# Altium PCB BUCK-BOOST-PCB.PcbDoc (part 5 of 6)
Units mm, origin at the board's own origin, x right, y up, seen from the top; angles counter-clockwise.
Board outline 99.9 x 67.48 mm, 4 copper layers (Top Layer, POWER, GND, Bottom Layer); 181 components, 110 nets, 560 pads, 389 vias.
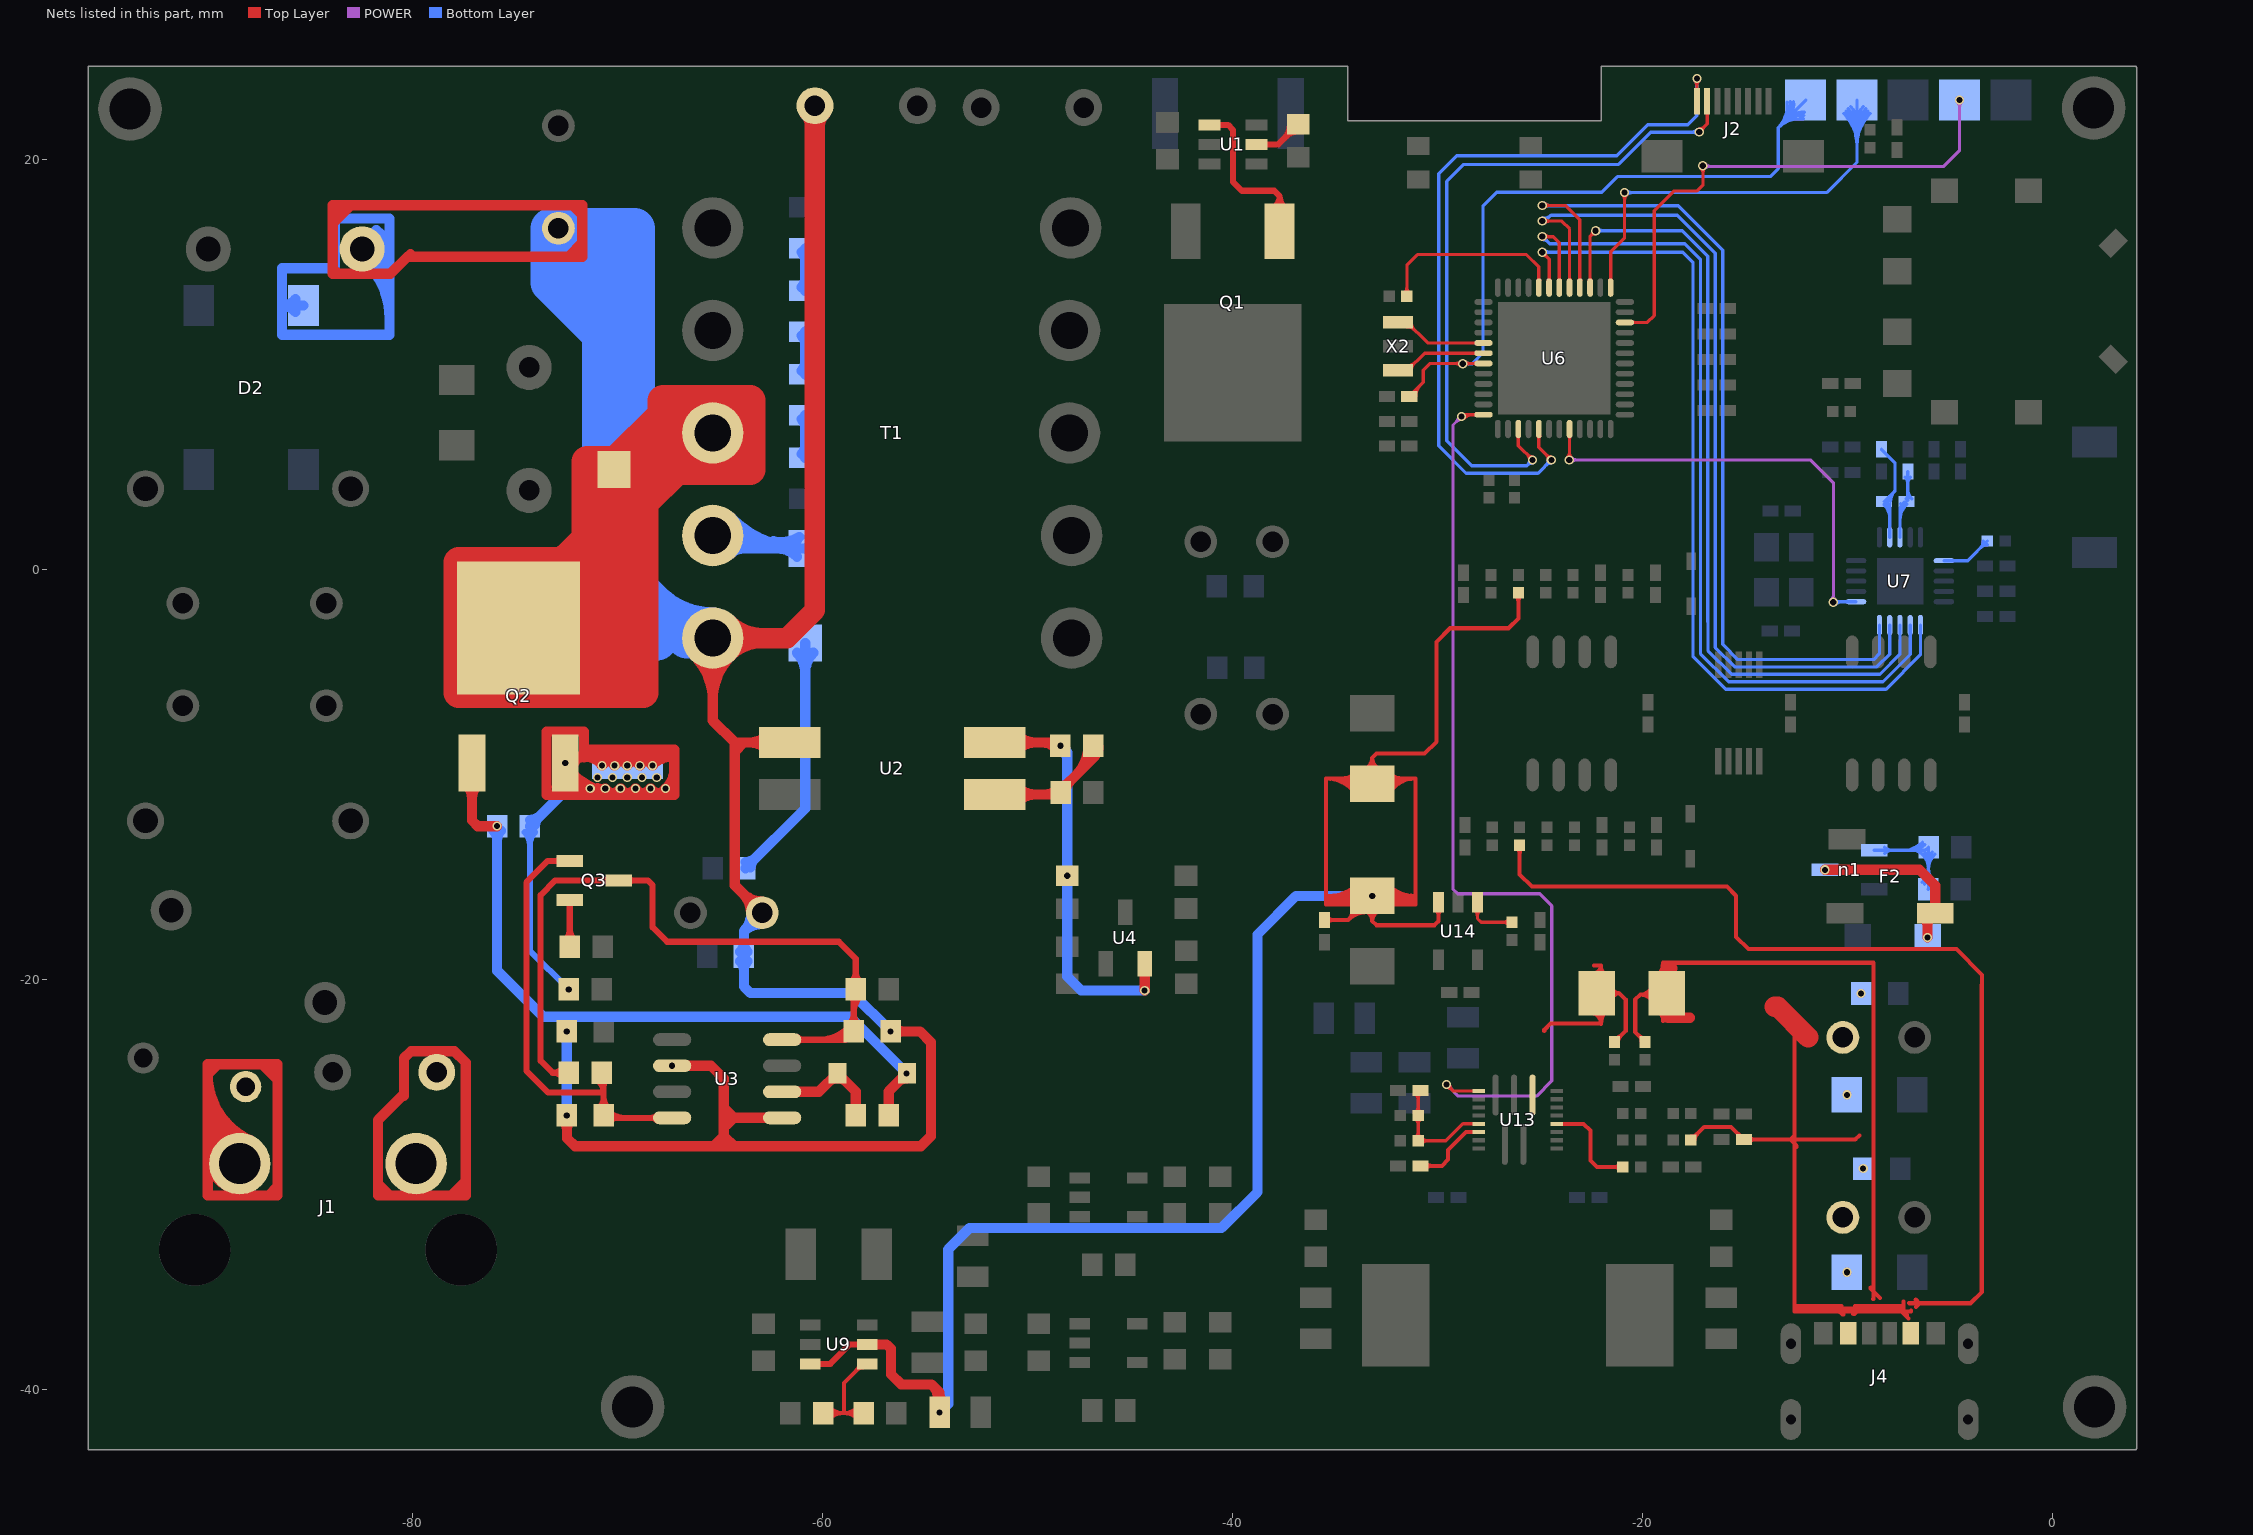
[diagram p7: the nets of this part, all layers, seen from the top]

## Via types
v1: diameter 0.45, hole 0.3, Top Layer to Bottom Layer, 389 vias

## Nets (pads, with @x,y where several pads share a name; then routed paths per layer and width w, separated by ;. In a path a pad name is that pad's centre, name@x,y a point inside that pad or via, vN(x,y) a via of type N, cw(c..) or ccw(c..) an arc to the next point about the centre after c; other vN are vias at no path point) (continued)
NetD1_1: D1.1 Q2.2 T1.3 | length 185.7
  Top Layer w1.5: Q2.2@-74.804,-2.841 Q2.2@-71.87,0.093 ; Q2.2@-72.595,-2.163 cw(c-68.589,-1.388) -71.474,1.497 ; Q2.2@-72.554,-2.591 cw(c-67.726,-2.591) -71.14,0.823 ; -72.258,0.714 cw(c-74.804,3.261) -74.804,-0.341 ccw(c-74.804,5.695) -70.536,1.427 ; Q2.2@-71.986,0.354 Q2.2@-72.617,0.354 ; -71.474,1.476 cw(c-66.828,1.476) -70.113,4.762 ccw(c-68.37,3.019) -70.836,3.019 ; -71.01,5.278 cw(c-71.01,4.131) D1.1@-70.199,4.942 ; D1.1@-70.199,4.762 cw(c-72.655,2.306) -69.181,2.306 ; D1.1@-70.177,4.748 cw(c-70.708,3.316) -69.181,3.316 ; D1.1@-70.176,4.748 cw(c-70.883,2.715) -68.731,2.715 ; D1.1@-70.16,4.744 cw(c-70.25,3.228) -68.731,3.228 ; D1.1@-70.113,4.942 cw(c-69.302,4.131) -69.302,5.278 ; D1.1@-69.999,5.323 -67.768,7.553 ; -67.768,6.422 -67.768,7.282 ; T1.3@-65.336,6.671 -66.486,5.522 ; Q2.2@-72.617,0.354 -77.719,0.354 -77.719,-5.989 Q2.2@-71.87,-5.989 ; Q2.2@-72.617,0.354 -71.474,1.497 ; Q2.2@-71.87,-5.989 Q2.2@-71.87,0.093 ; Q2.2@-71.87,-5.989 -71.218,-5.989 ; Q2.2@-71.87,0.093 -71.218,0.746 ; Q2.2@-71.87,0.093 -71.87,0.746 -71.218,0.746 ; -71.474,1.497 -70.836,2.136 ; -71.474,1.497 -71.474,5.278 D1.1@-70.836,5.278 ; -71.218,-5.989 -71.218,0.746 ; -71.218,-5.989 -70.156,-5.989 ; -71.218,0.745 cw(c-73.976,3.503) -74.501,-0.361 ccw(c-73.976,3.503) -71.218,0.745 ; -71.218,0.745 ccw(c-67.99,-2.483) -72.555,-2.555 cw(c-67.99,-2.483) -71.218,0.745 ; -71.218,0.746 -70.156,1.807 ; -70.836,2.136 D1.1@-70.836,5.278 ; -70.836,2.136 -70.725,2.136 -70.156,2.705 ; -70.836,2.136 -70.156,2.816 ; D1.1@-70.836,5.278 D1.1@-69.773,5.278 ; -70.156,-5.989 -69.181,-5.989 ; -70.156,-5.989 -70.156,1.807 ; -70.156,1.807 -70.156,2.705 ; -70.156,2.705 -69.181,3.68 ; -70.156,2.705 -70.156,2.816 ; -70.156,2.816 D1.1@-70.156,4.895 ; D1.1@-70.156,4.895 -68.731,4.895 ; D1.1@-70.156,4.895 D1.1@-69.773,5.278 ; D1.1@-69.773,5.278 -67.768,7.282 ; D1.1@-69.773,5.278 -67.113,5.278 ; -69.181,-5.989 -68.731,-5.989 -68.731,3.277 ; -69.181,-5.989 -69.181,3.68 ; -69.181,3.68 -68.731,4.13 ; -68.731,3.277 -68.731,4.13 ; -68.731,3.277 -67.113,4.895 ; -68.731,4.13 -68.731,4.895 ; -68.731,4.13 -67.967,4.895 ; -68.731,4.895 -67.967,4.895 ; -67.967,4.895 -67.113,4.895 ; -67.768,7.282 -67.113,7.938 ; -67.768,7.282 -67.768,7.553 ; -67.768,7.553 -67.113,8.208 ; -67.768,7.553 -67.768,8.256 -67.113,8.256 ; -67.113,4.895 -63.51,4.895 -63.51,8.256 -67.065,8.256 ; -67.113,4.895 -67.113,5.278 ; -67.113,4.895 -66.73,5.278 ; -67.113,5.278 -67.113,7.938 ; -67.113,5.278 -66.73,5.278 ; -67.113,7.938 -67.113,8.208 ; -67.113,8.208 -67.065,8.256 ; -67.113,8.208 -67.113,8.256 ; -67.113,8.256 -67.065,8.256 ; -66.73,5.278 -66.486,5.522 ; -66.73,5.278 -66.486,5.278 -66.486,5.522 ; -66.617,5.391 cw(c-65.336,4.111) T1.3@-65.336,5.921 ; -66.617,5.391 ccw(c-67.897,6.671) T1.3@-66.086,6.671 ; -66.617,5.391 cw(c-65.336,4.111) T1.3@-65.336,5.921 ; -66.617,5.391 ccw(c-67.897,6.671) T1.3@-66.086,6.671 ; -66.617,5.391 cw(c-65.336,4.111) T1.3@-65.336,5.921 ; -66.617,5.391 ccw(c-67.897,6.671) T1.3@-66.086,6.671 ; -66.486,5.522 cw(c-65.506,4.542) -65.396,5.924 ccw(c-65.506,4.542) -66.486,5.522 ; -66.486,5.522 ccw(c-67.466,6.502) -66.084,6.612 cw(c-67.466,6.502) -66.486,5.522
NetD3_1: D3.1 T1.4 | length 19
  Bottom Layer w0.5: T1.4@-65.336,1.671 -64.699,1.034 D3.1@-60.828,1.034 cw(c-60.828,6.112) T1.4@-64.446,2.548 ; T1.4@-65.158,1.847 ccw(c-63.217,3.759) -63.217,1.034 ; T1.4@-64.802,2.198 ccw(c-62.022,4.935) -62.022,1.034 ; T1.4@-64.453,0.787 cw(c-63.858,0.193) -63.858,1.034 ; -62.372,1.395 ccw(c-61.995,3.004) D3.1@-61.123,1.6 ; -61.958,1.298 cw(c-62.198,0.273) D3.1@-61.304,0.828 ; D3.1@-61.224,0.638 ccw(c-62.181,-0.319) -62.181,1.034 ccw(c-62.181,2.386) D3.1@-61.224,1.43
NetD3_2: D3.2 R5.1 | length 15.3
  Bottom Layer w0.5: R5.1@-63.744,-14.558 -60.828,-11.642 D3.2@-60.828,-3.566 ; R5.1@-63.744,-14.257 ccw(c-63.744,-13.53) -63.23,-14.044 ; R5.1@-63.493,-14.507 cw(c-63.012,-14.507) R5.1@-63.352,-14.166 ; D3.2@-61.224,-4.052 cw(c-62.181,-5.009) -60.828,-5.009 cw(c-59.475,-5.009) D3.2@-60.432,-4.052
NetD4_2: D4.2 Q2.1 R9.1 R10.1 | length 39.6
  Top Layer w0.5: Q2.1@-77.36,-10.458 cw(c-78.043,-11.14) -77.077,-11.14 cw(c-76.111,-11.14) Q2.1@-76.794,-10.458 ; Q2.1@-77.077,-9.425 -77.077,-12.229 -76.803,-12.503 v1(-75.855,-12.503) ; R9.1@-56.936,-26.385 ccw(c-57.363,-25.958) -56.759,-25.958 ccw(c-56.154,-25.958) R9.1@-56.582,-26.385 ; R9.1@-56.759,-26.613 -56.759,-25.442 D4.2@-55.868,-24.551 ; D4.2@-56.286,-24.969 cw(c-55.868,-25.388) D4.2@-55.868,-24.796
  Bottom Layer w0.5: R10.1@-76.032,-12.731 cw(c-76.459,-13.158) -75.855,-13.158 cw(c-75.25,-13.158) R10.1@-75.678,-12.731 ; v1(-75.855,-12.503) -75.855,-19.562 -73.61,-21.806 -58.644,-21.806 v1(-55.883,-24.567)
NetD11_2: D11.2 F2.2 n1.3 | length 10.3
  Top Layer w0.5: v1(-11.089,-14.634) -6.481,-14.634 -5.715,-15.401 F2.2@-5.715,-16.755 -6.087,-17.127 v1(-6.087,-17.937) ; F2.2@-6.291,-16.932 cw(c-6.785,-17.425) -6.087,-17.425 ; -6.087,-17.292 cw(c-5.578,-17.292) F2.2@-5.938,-16.932 ; F2.2@-5.891,-16.578 ccw(c-6.318,-16.151) -5.715,-16.151 ccw(c-5.111,-16.151) F2.2@-5.538,-16.578
NetF1_2: F1.2 J1.1 | length 23.4
  Top Layer w0.5: -80.4,-25.649 -80.4,-25.573 ; -80.4,-25.389 -80.4,-25.573 ; -81.657,-29.964 -81.657,-30.523 -81.098,-30.523 ; -81.657,-29.964 -81.657,-29.957 ; -81.657,-29.964 -81.661,-29.961 -81.657,-29.957 ; -81.657,-29.964 -81.098,-30.523 ; -81.657,-29.957 -81.657,-26.83 -80.4,-25.573 ; -81.098,-30.523 -78.083,-30.523 ; -80.4,-25.573 -80.4,-23.821 -80.056,-23.477 -77.936,-23.477 -77.382,-24.031 -77.382,-29.822 ; -78.083,-30.523 -77.382,-29.822 ; -78.083,-30.523 -77.382,-30.523 -77.382,-29.822
NetJ1_2: J1.2 NTC1.1 | length 40.2
  Top Layer w0.5: -89.969,-28.481 ccw(c-88.187,-28.481) J1.2@-88.92,-30.105 ; -89.969,-27.706 ccw(c-87.837,-27.706) J1.2@-88.714,-29.65 ; -89.969,-26.932 ccw(c-87.487,-26.932) J1.2@-88.509,-29.194 ; -89.969,-26.158 ccw(c-87.138,-26.158) J1.2@-88.303,-28.738 ; -89.969,-25.383 ccw(c-86.788,-25.383) J1.2@-88.097,-28.283 ; J1.2@-87.891,-27.827 cw(c-86.439,-24.609) -89.969,-24.609 ; -89.969,-24.609 -89.969,-29.902 -89.968,-29.903 -89.968,-30.518 -86.99,-30.518 ; -89.969,-24.609 -89.473,-24.112 ; -89.969,-24.609 -89.969,-24.112 -89.473,-24.112 ; -89.473,-24.112 -87.307,-24.112 ; -87.307,-24.112 -86.57,-24.85 ; -87.307,-24.112 -86.57,-24.112 -86.57,-24.85 ; -86.99,-30.518 -86.57,-30.098 ; -86.99,-30.518 -86.57,-30.518 -86.57,-30.098 ; -86.57,-30.098 -86.57,-24.85
NetL2_1: L2.1 L3.2 U7.13 | length 6.5
  Bottom Layer w0.16: U7.13@-7.434,1.586 -7.434,3.012 ; -7.434,2.407 cw(c-6.319,2.407) L3.2@-7.107,3.195 ; -7.434,2.793 cw(c-6.705,2.793) L3.2@-7.22,3.308 ; L3.2@-7.405,3.234 cw(c-7.563,3.141) -7.434,3.012 ; L2.1@-7.186,4.528 cw(c-7.511,4.204) -7.052,4.204 cw(c-6.593,4.204) L2.1@-6.918,4.528 ; L3.2@-7.126,3.464 ccw(c-7.304,3.642) -7.052,3.642 ; -7.052,3.934 ccw(c-6.387,3.934) L3.2@-6.857,3.464 ; L2.1@-7.052,4.788 -7.052,3.394 L3.2@-7.117,3.33 -7.434,3.012
NetL3_1: L3.1 L4.1 U7.12 | length 7.2
  Bottom Layer w0.16: L4.1@-8.333,5.878 -8.333,5.849 -7.673,5.189 -7.673,3.863 ; L3.1@-8.216,3.195 cw(c-8.897,2.514) -7.934,2.514 ; L3.1@-8.103,3.308 cw(c-8.511,2.9) -7.934,2.9 ; L3.1@-8.052,3.33 cw(c-7.684,3.332) L3.1@-7.944,3.592 ; L3.1@-7.939,3.204 ccw(c-7.857,3.133) -7.934,3.057 ; U7.12@-7.934,1.586 -7.934,3.057 ; L3.1@-7.892,3.331 cw(c-7.146,3.336) -7.673,3.863 ; -7.934,3.057 L3.1@-8.207,3.33 -7.673,3.863
Netn1_1: n1.1 R21.1 R22.1 | length 13.1
  Bottom Layer w0.16: n1.1@-8.689,-13.684 -6.19,-13.684 R22.1@-6.039,-13.533 -6.039,-15.566 R21.1@-6.058,-15.585 ; n1.1@-8.184,-13.84 cw(c-7.808,-14.215) -7.808,-13.684 cw(c-7.808,-13.153) n1.1@-8.184,-13.529 ; -7.296,-13.684 ccw(c-7.296,-12.327) R22.1@-6.336,-13.287 ; -6.91,-13.684 ccw(c-6.91,-12.713) R22.1@-6.223,-13.4 ; -6.812,-13.684 cw(c-6.812,-14.357) -6.336,-13.881 cw(c-7.054,-14.599) -6.039,-14.599 cw(c-5.024,-14.599) R22.1@-5.742,-13.881 ; R21.1@-6.355,-15.237 ccw(c-7.119,-14.474) -6.039,-14.474 ; R21.1@-6.242,-15.35 ccw(c-6.733,-14.86) -6.039,-14.86 ; R22.1@-6.223,-13.768 cw(c-6.667,-14.212) -6.039,-14.212 cw(c-5.41,-14.212) R22.1@-5.855,-13.768 ; -6.039,-14.952 ccw(c-5.475,-14.952) R21.1@-5.874,-15.35 ; -6.039,-14.566 ccw(c-5.089,-14.566) R21.1@-5.761,-15.237
NetQ1_1: Q1.1 U1.1 | length 9.5
  Top Layer w0.3: U1.1@-41.12,21.693 -40.204,21.693 -39.964,21.453 -39.964,18.921 -39.526,18.482 -37.954,18.482 -37.691,18.219 ; U1.1@-40.768,21.611 cw(c-40.57,21.413) -40.57,21.693 cw(c-40.57,21.973) U1.1@-40.768,21.775 ; Q1.1@-38.014,17.609 ccw(c-38.428,18.219) -37.691,18.219 ; Q1.1@-37.691,16.947 -37.691,18.219 ; Q1.1@-37.368,17.609 cw(c-36.954,18.219) -37.691,18.219
NetQ2_3: Q2.3 R10.2 R11.1 R12.2 | length 73.8
  Top Layer w0.5: Q2.3@-72.956,-10.599 ccw(c-72.063,-9.706) -72.063,-10.969 ; Q2.3@-72.602,-10.245 ccw(c-70.856,-8.499) -70.856,-10.969 ; Q2.3@-72.549,-9.407 cw(c-71.834,-10.122) -71.834,-9.111 ; v1(-72.531,-9.425) -72.531,-9.111 -71.617,-9.111 ; Q2.3@-72.249,-9.892 ccw(c-69.648,-7.292) -69.648,-10.969 ; Q2.3@-72.143,-9.522 cw(c-71.617,-9.654) -71.617,-9.111 ; Q2.3@-71.992,-10.6 ccw(c-71.54,-9.821) v1@-71.309,-10.691 ; -71.985,-10.969 ccw(c-71.985,-9.997) v1@-71.298,-10.684 ; -71.617,-9.139 -71.617,-9.111 ; v1@-71.333,-10.684 ccw(c-70.646,-9.997) -70.646,-10.969 ; -71.249,-10.969 ccw(c-71.249,-9.997) v1@-70.562,-10.684 ; -71.129,-9.111 cw(c-71.129,-10.563) v1@-70.103,-9.536 ; -70.958,-10.65 ccw(c-70.716,-10.205) v1@-70.573,-10.691 ; v1@-70.752,-9.536 cw(c-69.725,-10.563) -69.725,-9.111 ; v1@-70.715,-9.538 ccw(c-71.617,-10.277) -71.617,-9.111 ; v1@-70.6,-10.682 ccw(c-70.166,-10.349) -70.237,-10.891 ; v1@-70.597,-10.684 ccw(c-69.91,-9.997) -69.91,-10.969 ; -70.516,-9.111 cw(c-70.516,-10.563) v1@-69.489,-9.536 ; -70.513,-10.969 ccw(c-70.513,-9.997) v1@-69.826,-10.684 ; v1@-70.138,-9.536 cw(c-69.112,-10.563) -69.112,-9.111 ; -69.903,-9.111 cw(c-69.903,-10.563) v1@-68.876,-9.536 ; v1@-69.862,-10.684 ccw(c-69.175,-9.997) -69.175,-10.969 ; -69.777,-10.969 ccw(c-69.777,-9.997) v1@-69.09,-10.684 ; v1@-69.525,-9.536 cw(c-68.498,-10.563) -68.498,-9.111 ; -69.289,-9.111 cw(c-69.289,-10.563) v1@-68.263,-9.536 ; v1@-69.126,-10.684 ccw(c-68.439,-9.997) -68.439,-10.969 ; -69.042,-10.969 ccw(c-69.042,-9.997) v1@-68.355,-10.684 ; v1@-68.911,-9.536 cw(c-67.885,-10.563) -67.885,-9.111 ; v1@-68.39,-10.684 ccw(c-67.703,-9.997) -67.703,-10.969 ; -68.306,-10.969 ccw(c-68.306,-9.997) v1@-67.619,-10.684 ; v1@-68.298,-9.536 cw(c-67.271,-10.563) -67.271,-9.111 ; v1@-67.659,-10.677 ccw(c-67.211,-10.479) -67.211,-10.969 ; -67.211,-9.7 cw(c-68.603,-9.7) v1@-67.619,-10.684 ; -67.211,-9.7 cw(c-68.603,-9.7) v1@-67.619,-10.684 ; -71.617,-9.111 -71.617,-8.768 ; -71.617,-9.111 -67.211,-9.111 ; -71.617,-8.768 -67.211,-8.768 -67.211,-9.111 ; -71.617,-8.768 -71.617,-7.889 -73.445,-7.889 -73.445,-10.969 -67.211,-10.969 ; -67.211,-10.969 -67.211,-9.111 ; -67.211,-10.969 -67.211,-9.111 ; v1@-71.335,-10.682 ccw(c-70.736,-10.224) -70.836,-10.972 cw(c-70.736,-10.224) v1@-71.335,-10.682
  Bottom Layer w0.3: R10.2@-74.502,-12.802 cw(c-75.1,-13.4) -74.254,-13.4 cw(c-73.408,-13.4) R10.2@-74.007,-12.802 ; R10.2@-74.254,-12.503 -74.254,-18.57 v1(-72.361,-20.463)
  Bottom Layer w0.5: R10.2@-74.254,-12.503 -72.531,-10.78 v1(-72.531,-9.425) ; R10.2@-74.254,-12.202 ccw(c-74.254,-11.475) -73.74,-11.989 ; R10.2@-74.004,-12.452 cw(c-73.522,-12.452) R10.2@-73.863,-12.112
  other v1: -71.316,-10.667 -70.58,-10.667 -69.844,-10.667 -69.108,-10.667 -68.372,-10.667 -67.636,-10.667 -70.955,-10.126 -70.233,-10.126 -69.51,-10.126 -68.788,-10.126 -68.066,-10.126 -70.734,-9.554 -70.121,-9.554 -69.507,-9.554 -68.894,-9.554 -68.28,-9.554
NetQ3_2: Q3.2 R19.1 | length 4.2
  Top Layer w0.254: R19.1@-72.315,-18.381 R19.1@-72.304,-18.392
  Top Layer w0.3: R19.1@-72.551,-18.094 ccw(c-73.123,-17.522) -72.315,-17.522 ; Q3.2@-72.421,-16.207 cw(c-72.677,-16.463) -72.315,-16.463 cw(c-71.953,-16.463) Q3.2@-72.209,-16.207 ; R19.1@-72.315,-18.381 Q3.2@-72.315,-16.101 ; -72.315,-17.469 ccw(c-71.431,-17.469) R19.1@-72.056,-18.094
NetR3_1: R3.1 R6.2 | length 4
  Bottom Layer w0.5: R6.2@-61.01,13.779 ccw(c-61.436,14.204) -60.834,14.204 ccw(c-60.233,14.204) R6.2@-60.658,13.779 ; R3.1@-61.011,15.496 cw(c-61.439,15.069) -60.834,15.069 cw(c-60.23,15.069) R3.1@-60.657,15.496 ; R6.2@-60.834,13.603 R3.1@-60.834,15.673
NetR4_2: R4.2 U1.5 | length 4.2
  Top Layer w0.3: U1.5@-38.822,20.743 -37.756,20.743 R4.2@-36.78,21.718 ; U1.5@-38.47,20.661 cw(c-38.272,20.463) -38.272,20.743 cw(c-38.272,21.023) U1.5@-38.47,20.825 ; -37.465,21.033 ccw(c-38.15,21.718) R4.2@-37.182,21.718 ; -37.343,21.156 cw(c-36.831,20.645) R4.2@-36.831,21.368
NetR6_1: R6.1 R7.2 | length 4
  Bottom Layer w0.5: R7.2@-61.01,9.71 ccw(c-61.436,10.135) -60.834,10.135 ccw(c-60.233,10.135) R7.2@-60.658,9.71 ; R6.1@-61.011,11.427 cw(c-61.439,11) -60.834,11 cw(c-60.23,11) R6.1@-60.657,11.427 ; R7.2@-60.834,9.534 R6.1@-60.834,11.604
NetR7_1: R7.1 R8.2 | length 4
  Bottom Layer w0.5: R8.2@-61.01,5.641 ccw(c-61.436,6.066) -60.834,6.066 ccw(c-60.233,6.066) R8.2@-60.658,5.641 ; R7.1@-61.011,7.358 cw(c-61.439,6.931) -60.834,6.931 cw(c-60.23,6.931) R7.1@-60.657,7.358 ; R8.2@-60.834,5.465 R7.1@-60.834,7.535
NetR14_2: R14.2 R15.2 U2.1 | length 12.5
  Top Layer w0.5: U2.1@-51.575,-10.961 -48.476,-10.961 R14.2@-48.376,-10.861 -48.376,-10.773 -46.778,-9.176 ; U2.1@-50.472,-11.315 cw(c-49.618,-12.168) -49.618,-10.961 cw(c-49.618,-9.754) U2.1@-50.472,-10.608 ; -49.099,-10.961 ccw(c-49.099,-10.188) R14.2@-48.553,-10.735 ; R14.2@-48.376,-10.56 ccw(c-48.376,-10.045) R14.2@-48.011,-10.409 ; R14.2@-48.125,-10.81 cw(c-47.432,-10.81) R14.2@-47.922,-10.32 ; -47.589,-9.986 ccw(c-48.942,-8.633) R15.2@-47.028,-8.633 ; R15.2@-46.94,-8.824 cw(c-47.24,-9.176) -46.778,-9.176 ; R15.2@-46.778,-8.583 -46.778,-9.176 ; R15.2@-46.735,-9.133 ccw(c-47.235,-8.633) R15.2@-46.528,-8.633 ; R15.2@-46.616,-8.824 ccw(c-46.316,-9.176) -46.778,-9.176
NetR15_1: R15.1 R16.2 U2.2 U4.2 | length 25
  Top Layer w0.5: U2.2@-51.575,-8.421 -48.539,-8.421 v1(-48.378,-8.583) ; U2.2@-50.472,-8.775 cw(c-49.618,-9.628) -49.618,-8.421 cw(c-49.618,-7.214) U2.2@-50.472,-8.068 ; -49.25,-8.421 cw(c-49.25,-9.403) R15.1@-48.555,-8.709 ; R15.1@-48.838,-8.545 ccw(c-48.531,-8.013) R15.1@-48.372,-8.607 ; R15.1@-48.707,-8.421 cw(c-48.707,-8.912) R15.1@-48.36,-8.565 ; v1(-44.271,-20.522) -44.266,-20.517 U4.2@-44.266,-19.206
  Bottom Layer w0.5: v1(-48.378,-8.583) -48.047,-8.914 v1(-48.047,-14.922) -48.047,-19.836 -47.361,-20.522 v1(-44.271,-20.522) ; v1@-48.368,-8.56 cw(c-48.583,-9.051) -48.047,-9.051 ; v1@-48.36,-8.565 cw(c-49.118,-9.322) -48.047,-9.322
NetR25_1: R25.1 U7.16 | length 3.2
  Bottom Layer w0.16: U7.16@-5.291,0.443 -4.127,0.443 R25.1@-3.167,1.404 ; -3.513,1.058 ccw(c-3.86,1.404) R25.1@-3.37,1.404 ; -3.482,1.089 cw(c-3.18,0.786) R25.1@-3.18,1.214
NetR28_2: R28.2 U6.44 | length 10.4
  Top Layer w0.16: R28.2@-31.616,13.473 ccw(c-31.94,13.798) -31.482,13.798 ccw(c-31.023,13.798) R28.2@-31.347,13.473 ; R28.2@-31.482,13.339 -31.482,14.862 -30.969,15.375 -25.648,15.375 -25.046,14.773 U6.44@-25.046,13.763 ; U6.44@-25.088,14.115 ccw(c-25.191,14.218) -25.046,14.218 ccw(c-24.901,14.218) U6.44@-25.003,14.115
NetR29_2: R29.2 R30.1 U9.4 | length 8.7
  Top Layer w0.2: R30.1@-59.945,-41.129 -58.943,-41.129 ; R30.1@-59.662,-41.412 cw(c-58.979,-42.095) -58.979,-41.129 cw(c-58.979,-40.162) R30.1@-59.662,-40.846 ; -58.315,-39.032 ccw(c-58.614,-38.732) U9.4@-58.191,-38.732 ; -58.315,-39.031 cw(c-58.016,-39.329) U9.4@-58.016,-38.907 ; R29.2@-58.259,-41.412 ccw(c-58.942,-42.095) -58.942,-41.129 ccw(c-58.942,-40.162) R29.2@-58.259,-40.846 ; R29.2@-57.975,-41.129 -58.943,-41.129 ; U9.4@-57.791,-38.732 -58.016,-38.732 -58.943,-39.659 -58.943,-41.129
NetR47_2: R47.2 U13.17 | length 5.6
  Top Layer w0.2: U13.17@-24.178,-27.022 -22.862,-27.022 -22.536,-27.348 -22.536,-28.804 -22.215,-29.125 R47.2@-20.948,-29.125 ; R47.2@-21.081,-29.245 ccw(c-21.371,-29.535) -21.371,-29.125 ccw(c-21.371,-28.714) R47.2@-21.081,-29.005
NetR50_2: R50.2 R51.2 U13.1 | length 15.5
  Top Layer w0.2: -24.782,-22.502 -24.782,-22.435 -24.478,-22.131 -22.014,-22.131 R51.2@-22.014,-20.656 ; R51.2@-22.43,-21.61 cw(c-22.571,-22.149) -22.014,-22.149 cw(c-21.038,-22.149) R51.2@-21.697,-21.429 ; R51.2@-22.379,-21.417 cw(c-22.503,-21.89) -22.014,-21.89 ; R51.2@-22.35,-19.686 ccw(c-22.41,-19.295) -22.014,-19.295 ; -22.349,-19.295 -22.014,-19.295 ; R51.2@-22.319,-19.884 ccw(c-22.374,-19.528) -22.014,-19.528 ; R51.2@-22.23,-20.656 R51.2@-22.014,-20.656 ; R51.2@-21.746,-19.843 cw(c-21.321,-19.295) -22.014,-19.295 ; R51.2@-21.487,-20.923 cw(c-21.109,-21.059) -21.109,-20.656 ; R51.2@-21.487,-20.39 ccw(c-21.109,-20.254) -21.109,-20.656 ; R50.2@-21.354,-23.032 -20.81,-22.488 -20.81,-20.955 -21.109,-20.656 ; R50.2@-21.354,-22.849 ccw(c-21.354,-22.407) -21.042,-22.72 ; R50.2@-21.184,-23.019 cw(c-20.804,-23.019) -21.073,-22.75 ; R51.2@-22.014,-20.656 -21.109,-20.656 ; R51.2@-22.014,-20.656 -22.014,-19.295
NetR54_1: R54.1 U14.1 | length 4
  Top Layer w0.16: U14.1@-28.177,-16.587 cw(c-28.51,-16.92) -28.039,-16.92 cw(c-27.568,-16.92) U14.1@-27.901,-16.587 ; U14.1@-28.039,-16.224 -28.039,-17.01 -27.858,-17.191 R54.1@-26.36,-17.191 ; R54.1@-26.494,-17.325 ccw(c-26.819,-17.65) -26.819,-17.191 ccw(c-26.819,-16.732) R54.1@-26.494,-17.057
NetU6_5: U6.5 X2.1 | length 5.6
  Top Layer w0.16: X2.1@-31.914,12.07 -31.482,12.07 -30.475,11.063 U6.5@-27.746,11.063 ; X2.1@-31.489,11.85 cw(c-31.489,11.302) -31.102,11.69 ; X2.1@-31.269,12.07 ccw(c-30.755,12.07) -31.119,11.707 ; U6.5@-28.098,11.02 ccw(c-28.201,10.918) -28.201,11.063 ccw(c-28.201,11.208) U6.5@-28.098,11.105
NetU6_6: U6.6 X2.2 | length 5.6
  Top Layer w0.16: X2.2@-31.914,9.734 -31.91,9.73 -31.453,9.73 -30.62,10.563 U6.6@-27.746,10.563 ; X2.2@-31.489,9.954 ccw(c-31.489,10.583) -31.045,10.138 ; X2.2@-31.269,9.734 cw(c-30.836,9.734) -31.142,10.04 ; U6.6@-28.098,10.52 ccw(c-28.201,10.418) -28.201,10.563 ccw(c-28.201,10.707) U6.6@-28.098,10.605
NRF_CE: U6.43 U7.1 | length 43.9
  Top Layer w0.16: v1@-24.881,15.343 cw(c-24.881,14.993) -24.633,15.24 cw(c-24.386,15.488) v1@-24.736,15.488 ; v1(-24.881,15.488) -24.545,15.152 U6.43@-24.545,13.763 ; U6.43@-24.588,14.115 ccw(c-24.69,14.218) -24.545,14.218 ccw(c-24.4,14.218) U6.43@-24.503,14.115
  Bottom Layer w0.16: v1(-24.881,15.488) -18.021,15.488 -17.53,14.996 -17.53,-3.345 -17.523,-3.352 -17.523,-4.236 -15.939,-5.821 -8.113,-5.821 -6.434,-4.142 U7.1@-6.434,-2.7 ; v1@-24.778,15.385 cw(c-24.531,15.138) -24.531,15.488 cw(c-24.531,15.838) v1@-24.778,15.59
NRF_CSN: U6.42 U7.2 | length 44.6
  Top Layer w0.16: v1(-24.881,16.248) -24.346,16.248 -24.047,15.95 U6.42@-24.047,13.763 ; v1@-24.778,16.146 cw(c-24.531,15.898) -24.531,16.248 cw(c-24.531,16.599) v1@-24.778,16.351 ; U6.42@-24.09,14.115 ccw(c-24.192,14.218) -24.047,14.218 ccw(c-23.903,14.218) U6.42@-24.005,14.115
  Bottom Layer w0.16: v1@-24.881,16.103 cw(c-24.881,15.717) -24.607,15.99 ; v1@-24.862,16.245 -24.517,15.9 -17.924,15.9 -17.163,15.139 -17.163,-4.087 -15.789,-5.461 -8.262,-5.461 -6.934,-4.133 U7.2@-6.934,-2.7 ; v1@-24.736,16.248 ccw(c-24.422,16.248) -24.644,16.027
NRF_IRQ: U6.20 U7.6 | length 24.3
  Top Layer w0.16: v1@-23.665,5.461 ccw(c-23.949,5.745) -23.547,5.745 ; U6.20@-23.589,6.512 cw(c-23.692,6.409) -23.547,6.409 cw(c-23.402,6.409) U6.20@-23.505,6.512 ; v1(-23.562,5.358) -23.547,5.373 U6.20@-23.547,6.864 ; v1@-23.547,5.302 v1@-23.547,5.358 ; -23.547,5.671 ccw(c-23.249,5.671) v1@-23.46,5.461
  POWER w0.16: v1(-23.562,5.358) -11.811,5.358 -10.674,4.222 -10.674,-1.572 v1@-10.66,-1.586 ; v1@-23.46,5.256 cw(c-23.212,5.008) -23.212,5.358 cw(c-23.212,5.708) v1@-23.46,5.461 ; v1@-10.792,-1.484 ccw(c-11.076,-1.199) -10.674,-1.199 ; -10.674,-1.273 ccw(c-10.376,-1.273) v1@-10.587,-1.484
  Bottom Layer w0.16: v1(-10.69,-1.586) -10.66,-1.557 U7.6@-9.577,-1.557 ; v1@-10.587,-1.689 cw(c-10.268,-2.008) -10.268,-1.557 ; v1@-10.587,-1.484 ccw(c-10.411,-1.308) -10.411,-1.557
NRF_MISO: U6.40 U7.5 | length 45
  Top Layer w0.16: v1(-24.881,17.77) -23.749,17.77 -23.047,17.068 U6.40@-23.047,13.763 ; v1@-24.778,17.667 cw(c-24.531,17.42) -24.531,17.77 cw(c-24.531,18.12) v1@-24.778,17.872 ; U6.40@-23.089,14.115 ccw(c-23.192,14.218) -23.047,14.218 ccw(c-22.902,14.218) U6.40@-23.004,14.115
  Bottom Layer w0.16: v1@-24.778,17.667 cw(c-24.567,17.457) -24.567,17.755 ; v1@-24.778,17.872 ccw(c-24.494,18.157) -24.494,17.755 ; v1@-24.762,17.77 -24.747,17.755 -18.252,17.755 -16.079,15.582 -16.079,-3.644 -15.345,-4.378 -8.706,-4.378 -8.434,-4.106 U7.5@-8.434,-2.7
NRF_MOSI: U6.41 U7.4 | length 44.6
  Top Layer w0.16: v1(-24.881,17.009) -23.933,17.009 -23.547,16.623 U6.41@-23.547,13.763 ; v1@-24.778,16.907 cw(c-24.531,16.659) -24.531,17.009 cw(c-24.531,17.359) v1@-24.778,17.112 ; U6.41@-23.589,14.115 ccw(c-23.692,14.218) -23.547,14.218 ccw(c-23.402,14.218) U6.41@-23.505,14.115
  Bottom Layer w0.16: v1@-24.863,17.153 ccw(c-24.802,17.638) -24.456,17.292 ; v1@-24.776,16.972 -24.456,17.292 ; U7.4@-7.934,-2.7 -7.934,-4.115 -8.557,-4.738 -15.495,-4.738 -16.439,-3.793 -16.439,15.433 -18.299,17.292 -24.456,17.292
NRF_SCK: U6.39 U7.3 | length 41.1
  Top Layer w0.16: U6.39@-22.589,14.115 ccw(c-22.691,14.218) -22.546,14.218 ccw(c-22.401,14.218) U6.39@-22.504,14.115 ; U6.39@-22.546,13.763 -22.546,16.266 v1(-22.276,16.537) ; v1@-22.421,16.537 cw(c-22.771,16.537) -22.523,16.289 cw(c-22.276,16.042) v1@-22.276,16.392
  Bottom Layer w0.16: v1(-22.276,16.537) -18.052,16.537 -16.803,15.288 -16.803,-2.548 -16.799,-2.551 -16.799,-3.942 -15.644,-5.098 -8.408,-5.098 -7.434,-4.124 U7.3@-7.434,-2.7 ; v1@-22.173,16.434 cw(c-21.926,16.187) -21.926,16.537 cw(c-21.926,16.887) v1@-22.173,16.639
NRST: C37.2 pad.0@-12.029,22.907 U6.7 | length 41.6
  Top Layer w0.16: C37.2@-31.369,8.456 -30.684,9.141 -30.684,9.733 -30.353,10.065 -28.757,10.065 U6.7@-27.746,10.065 ; C37.2@-31.214,8.456 cw(c-30.84,8.456) C37.2@-31.105,8.721 ; C37.2@-31.054,8.456 cw(c-30.294,8.456) -30.831,8.994 ; -29.14,10.065 cw(c-29.14,9.667) v1@-28.859,9.948 ; -29.073,10.065 ccw(c-29.073,10.368) v1@-28.859,10.153 ; v1@-28.654,9.948 cw(c-28.373,9.667) -28.373,10.065 ; v1@-28.654,10.153 ccw(c-28.44,10.368) -28.44,10.065 ; U6.7@-28.098,10.022 ccw(c-28.201,9.92) -28.201,10.065 ccw(c-28.201,10.21) U6.7@-28.098,10.107
  Bottom Layer w0.16: v1(-28.757,10.051) -28.296,10.051 -27.774,10.573 -27.774,17.739 -27.097,18.416 -21.976,18.416 -21.213,19.18 -13.762,19.18 -13.376,19.566 -13.376,21.561 ; v1@-28.654,9.948 cw(c-28.407,9.701) -28.407,10.051 cw(c-28.407,10.401) v1@-28.654,10.153 ; pad.0@-12.943,22.802 cw(c-14.443,22.628) -13.376,21.561 ; pad.0@-12.784,22.82 cw(c-14.023,22.677) -13.141,21.795 cw(c-12.26,20.913) pad.0@-12.117,22.152 ; pad.0@-12.625,22.838 cw(c-13.604,22.725) -12.907,22.029 cw(c-12.211,21.333) pad.0@-12.098,22.311 ; pad.0@-12.135,21.993 ccw(c-12.308,20.493) -13.376,21.561 ; pad.0@-12.029,22.907 -13.376,21.561
OUT: D4.1 R9.2 U3.6 | length 7.4
  Top Layer w0.5: U3.6@-61.952,-25.46 -60.161,-25.46 D4.1@-59.253,-24.551 -58.359,-25.445 R9.2@-58.359,-26.613 ; D4.1@-59.671,-24.969 cw(c-59.253,-25.388) -59.253,-24.796 cw(c-59.253,-25.388) D4.1@-58.834,-24.969 ; R9.2@-58.536,-26.385 ccw(c-58.964,-25.958) -58.359,-25.958 ccw(c-57.755,-25.958) R9.2@-58.182,-26.385
PGND: C10.2 C11.2 C12.2 C13.2 C14.2 C15.1 C17.1 C18.1 D2.2 R12.1 T1.5 U2.3 U3.2 U3.5 | length 327.9
  Top Layer w0.5: -80.075,15.391 -80.194,15.272 ; C18.1@-72.637,-26.841 cw(c-73.098,-27.302) -72.446,-27.302 ; v1(-72.46,-26.613) -72.446,-26.627 -72.446,-27.724 -72.05,-28.12 -65.297,-28.12 ; -72.446,-27.234 cw(c-71.89,-27.234) C18.1@-72.283,-26.841 ; v1(-67.317,-24.19) -65.423,-24.19 -64.794,-24.818 -64.794,-26.246 ; T1.5@-66.22,-4.213 cw(c-68.354,-6.346) -65.336,-6.346 cw(c-62.319,-6.346) T1.5@-64.453,-4.213 ; T1.5@-65.867,-3.859 cw(c-67.147,-5.139) -65.336,-5.139 cw(c-63.526,-5.139) T1.5@-64.806,-3.859 ; T1.5@-65.336,-3.329 -65.336,-7.355 -64.27,-8.421 ; -64.256,-28.12 -64.291,-28.12 ; C13.2@-63.472,-16.73 ccw(c-64.8,-16.73) -63.861,-15.791 ccw(c-62.922,-14.852) C13.2@-62.922,-16.18 ; C13.2@-62.922,-16.73 -64.27,-15.382 -64.27,-8.866 ; U2.3@-62.679,-8.775 ccw(c-63.532,-9.628) -63.532,-8.421 ccw(c-63.532,-7.214) U2.3@-62.679,-8.068 ; U3.5@-61.952,-26.73 -64.31,-26.73 ; U2.3@-61.575,-8.421 -63.825,-8.421 ; C17.1@-56.68,-22.529 ccw(c-56.465,-22.377) C17.1@-56.333,-22.605 ; C17.1@-56.68,-22.5 cw(c-56.465,-22.653) C17.1@-56.333,-22.425 ; v1(-56.66,-22.515) -55.231,-22.515 -54.696,-23.049 -54.696,-27.631 -55.185,-28.12 -64.291,-28.12 ; C17.1@-56.483,-22.692 cw(c-56.055,-23.119) -56.055,-22.515 cw(c-56.055,-21.91) C17.1@-56.483,-22.338 ; -83.867,14.694 -83.867,16.9 ; -83.867,14.694 -83.867,14.435 -83.608,14.435 ; -83.867,14.694 -83.608,14.435 ; -83.867,16.9 -83.867,17.778 -82.989,17.778 ; -83.867,16.9 -82.989,17.778 ; -83.608,14.435 -81.062,14.435 -80.225,15.272 -80.194,15.272 ; -82.989,17.778 -72.156,17.778 ; -80.194,15.272 -72.372,15.272 ; -72.372,15.272 -71.703,15.272 -71.703,15.941 ; -72.372,15.272 -71.703,15.941 ; -72.156,17.778 -71.703,17.778 -71.703,17.324 ; -72.156,17.778 -71.703,17.324 ; -71.703,15.941 -71.703,17.324 ; -65.297,-28.12 -64.794,-27.617 ; -65.297,-28.12 -64.602,-28.12 ; -64.794,-27.617 -64.794,-27.929 -64.602,-28.12 ; -64.794,-27.617 -64.291,-28.12 ; -64.794,-27.617 -64.794,-27.041 ; -64.794,-27.041 -64.621,-27.041 -64.31,-26.73 ; -64.794,-27.041 -64.794,-26.787 ; -64.794,-26.787 -64.737,-26.73 -64.31,-26.73 ; -64.794,-26.787 -64.794,-26.246 ; -64.794,-26.246 -64.31,-26.73 ; -64.602,-28.12 -64.291,-28.12 ; -64.27,-8.866 -63.825,-8.421 ; -64.27,-8.866 -64.27,-8.421 ; -64.27,-8.421 -63.825,-8.421
  Top Layer w1: T1.5@-65.336,-3.329 -61.708,-3.329 -60.352,-1.972 C14.2@-60.352,22.63 ; T1.5@-64.629,-4.036 cw(c-62.922,-5.743) -62.922,-3.329 cw(c-62.922,-0.914) T1.5@-64.629,-2.622 ; C14.2@-60.635,22.347 cw(c-61.317,21.665) -60.352,21.665 cw(c-59.386,21.665) C14.2@-60.069,22.347
  Bottom Layer w0.5: D2.2@-85.691,12.572 ccw(c-86.34,12.055) -86.34,12.884 ; D2.2@-85.691,13.196 cw(c-86.34,13.713) -86.34,12.884 ; D2.2@-85.3,12.884 -86.34,12.884 ; -84.192,14.707 -86.34,14.707 -86.34,12.884 ; -83.861,14.815 -83.774,14.815 -83.774,17.134 -81.101,17.134 -81.101,11.466 -86.34,11.466 -86.34,12.884 ; C11.2@-82.648,15.363 cw(c-84.986,12.26) -81.101,12.26 ; C11.2@-82.348,15.762 cw(c-84.231,13.263) -81.101,13.263 ; C11.2@-82.047,16.162 cw(c-83.475,14.265) -81.101,14.265 ; -81.746,16.561 cw(c-82.72,15.268) -81.101,15.268 ; v1(-72.46,-26.613) v1(-72.46,-22.515) ; C12.2@-63.992,-19.089 cw(c-64.419,-19.516) -63.815,-19.516 cw(c-63.21,-19.516) C12.2@-63.638,-19.089 ; C12.2@-63.992,-18.633 ccw(c-64.419,-18.205) -63.815,-18.205 ccw(c-63.21,-18.205) C12.2@-63.638,-18.633 ; C13.2@-63.472,-16.75 cw(c-64.645,-16.792) -63.815,-17.622 ; C13.2@-62.942,-17.279 ccw(c-62.985,-18.453) -63.815,-17.622 ; C13.2@-62.922,-16.73 -63.815,-17.622 ; v1(-56.66,-22.515) -58.527,-20.648 -63.495,-20.648 -63.815,-20.328 C12.2@-63.815,-18.861 -63.815,-17.622
  Bottom Layer w2: -70.587,11.373 -70.668,11.454 ; -70.302,-4.1 -70.668,-4.1 R12.1@-70.668,-3.421 ; -69.152,-0.772 cw(c-71.801,-3.421) R12.1@-68.055,-3.421 ; R12.1@-68.611,-3.121 cw(c-67.731,-4.463) T1.5@-66.596,-3.329 ; -68.341,-1.584 ccw(c-65.336,1.42) T1.5@-65.336,-2.829 ; T1.5@-65.336,-3.329 T1.5@-66.596,-3.329 ; -73.194,14.689 -70.897,14.689 ; -73.194,14.689 -73.194,14.614 -70.707,12.127 ; -73.194,14.689 C10.2@-73.194,16.655 ; C10.2@-73.194,16.655 -73.218,16.655 -73.218,14.004 -70.707,11.493 ; C10.2@-73.194,16.655 C10.2@-72.863,16.655 ; C10.2@-72.863,16.655 -70.897,14.689 ; C10.2@-72.863,16.655 C10.2@-72.796,16.655 ; C10.2@-72.796,16.655 -70.83,14.689 ; C10.2@-72.796,16.655 -69.792,16.655 ; -70.897,14.689 -70.707,14.499 ; -70.897,14.689 -70.83,14.689 ; -70.83,14.689 -70.707,14.689 ; -70.83,14.689 -70.707,14.566 ; -70.707,11.493 -70.668,11.454 ; -70.707,11.493 -70.707,-3.421 R12.1@-70.668,-3.421 ; -70.707,11.493 -70.707,12.127 ; -70.707,12.127 -70.707,14.499 ; -70.707,14.499 -70.668,14.46 ; -70.707,14.499 -70.707,14.566 ; -70.707,14.566 -70.668,14.526 ; -70.707,14.566 -70.707,14.689 ; -70.707,14.689 -70.668,14.689 ; R12.1@-70.668,-3.421 R12.1@-69.501,-3.421 R12.1@-69.792,-3.13 ; R12.1@-70.668,-3.421 -70.668,11.454 ; -70.668,11.454 -70.668,14.46 ; -70.668,14.46 -70.457,14.249 ; -70.668,14.46 -70.668,14.526 ; -70.668,14.526 -70.457,14.316 ; -70.668,14.526 -70.668,14.689 ; -70.668,14.689 -70.457,14.689 -70.457,14.316 ; -70.457,14.249 -70.457,14.316 ; -70.457,14.249 -70.457,-2.465 R12.1@-69.792,-3.13 ; -70.457,14.316 -69.792,13.65 ; R12.1@-69.792,-3.13 -69.792,-0.133 ; -69.792,-0.133 -69.792,13.65 ; -69.792,-0.133 -69.165,-0.76 ; -69.792,13.65 -69.792,16.655 ; -69.792,16.655 -69.165,16.655 -69.165,-0.76 ; -69.165,-0.76 T1.5@-66.596,-3.329
RT: C18.2 Q3.1 R18.1 U3.4 | length 26.5
  Top Layer w0.3: Q3.1@-72.771,-14.307 ccw(c-73.027,-14.563) -73.027,-14.201 ccw(c-73.027,-13.839) Q3.1@-72.771,-14.095 ; Q3.1@-72.315,-14.201 -73.381,-14.201 -74.425,-15.245 -74.425,-24.445 -73.376,-25.494 -70.678,-25.494 -70.659,-25.513 ; R18.1@-70.976,-24.861 cw(c-71.499,-25.518) -70.659,-25.518 ; C18.2@-70.907,-26.314 ccw(c-71.505,-25.716) -70.659,-25.716 ccw(c-69.813,-25.716) C18.2@-70.411,-26.314 ; R18.1@-70.758,-24.536 -70.659,-24.635 -70.659,-25.513 ; -70.659,-25.193 cw(c-70.151,-25.193) R18.1@-70.51,-24.834 ; C18.2@-70.411,-26.911 cw(c-69.973,-27.35) -69.973,-26.73 ; C18.2@-70.411,-26.416 ccw(c-69.654,-25.658) -69.654,-26.73 ; U3.4@-68.051,-26.846 ccw(c-68.332,-27.128) -68.332,-26.73 ccw(c-68.332,-26.331) U3.4@-68.051,-26.613 ; U3.4@-67.317,-26.73 -70.542,-26.73 C18.2@-70.659,-26.613 -70.659,-25.513
SC_CE: U6.12 U13.4 | length 47.8
  Top Layer w0.16: v1@-29.544,-25.243 cw(c-29.544,-25.593) -29.296,-25.345 cw(c-29.049,-25.098) v1@-29.399,-25.098 ; v1(-29.544,-25.098) -29.219,-25.422 U13.4@-27.978,-25.422 ; v1(-28.815,7.479) -28.731,7.563 U6.12@-27.746,7.563 ; v1@-28.713,7.377 cw(c-28.263,6.927) -28.263,7.563 ; U6.12@-28.098,7.52 ccw(c-28.201,7.418) -28.201,7.563 ccw(c-28.201,7.708) U6.12@-28.098,7.605
  POWER w0.16: v1@-29.544,-25.243 cw(c-29.544,-25.593) -29.296,-25.345 cw(c-29.049,-25.098) v1@-29.399,-25.098 ; v1(-29.544,-25.098) -28.975,-25.667 -25.16,-25.667 -24.419,-24.926 -24.419,-16.396 -25.009,-15.806 -29.011,-15.806 -29.233,-15.584 -29.233,7.061 v1(-28.815,7.479) ; v1@-28.96,7.479 cw(c-29.31,7.479) -29.063,7.232 cw(c-28.815,6.984) v1@-28.815,7.334
SCL: J2.7 U6.15 | length 36.9
  Top Layer w0.16: U6.15@-26.089,6.512 cw(c-26.191,6.409) -26.046,6.409 cw(c-25.902,6.409) U6.15@-26.004,6.512 ; U6.15@-26.046,6.864 -26.046,6.055 v1(-25.349,5.358) ; v1@-25.494,5.358 ccw(c-25.844,5.358) -25.597,5.606 ccw(c-25.349,5.853) v1@-25.349,5.503 ; v1(-17.226,21.355) -16.838,21.744 J2.7@-16.838,22.85 ; v1@-17.226,21.5 ccw(c-17.226,21.85) -16.979,21.603 ccw(c-16.731,21.355) v1@-17.081,21.355 ; J2.7@-16.887,22.301 cw(c-17.007,22.181) -16.838,22.181 cw(c-16.669,22.181) J2.7@-16.788,22.301
  Bottom Layer w0.16: v1@-25.494,5.358 cw(c-25.844,5.358) -25.597,5.111 cw(c-25.349,4.863) v1@-25.349,5.213 ; v1(-25.349,5.358) -25.637,5.07 -28.329,5.07 -29.541,6.283 -29.541,18.938 -28.71,19.77 -21.159,19.77 -19.587,21.342 v1@-17.226,21.342 ; -17.607,21.342 ccw(c-17.607,21.736) v1@-17.329,21.458 ; -17.546,21.342 cw(c-17.546,21.036) v1@-17.329,21.253
SDA: J2.8 U6.17 | length 40.7
  Top Layer w0.16: U6.17@-25.088,6.512 cw(c-25.191,6.409) -25.046,6.409 cw(c-24.901,6.409) U6.17@-25.003,6.512 ; U6.17@-25.046,6.864 -25.046,5.967 v1(-24.437,5.358) ; v1@-24.582,5.358 ccw(c-24.932,5.358) -24.685,5.606 ccw(c-24.437,5.853) v1@-24.437,5.503 ; v1@-17.442,23.855 cw(c-17.693,23.604) -17.338,23.604 ; J2.8@-17.387,23.4 ccw(c-17.507,23.519) -17.338,23.519 ccw(c-17.169,23.519) J2.8@-17.288,23.4 ; v1(-17.339,23.957) -17.338,23.956 J2.8@-17.338,22.85 ; -17.338,23.611 cw(c-16.993,23.611) v1@-17.237,23.855
  Bottom Layer w0.16: v1@-24.582,5.358 cw(c-24.932,5.358) -24.685,5.111 cw(c-24.437,4.863) v1@-24.437,5.213 ; v1(-24.437,5.358) -25.086,4.71 -28.6,4.71 -29.934,6.044 -29.934,19.313 -29.049,20.198 -21.241,20.198 -19.736,21.702 -17.783,21.702 -17.339,22.146 v1(-17.339,23.957) ; v1@-17.442,23.855 cw(c-17.689,23.607) -17.339,23.607 cw(c-16.989,23.607) v1@-17.237,23.855
SWCLK: pad.1 U6.37 | length 31.6
  Top Layer w0.16: U6.37@-21.588,14.115 ccw(c-21.69,14.218) -21.546,14.218 ccw(c-21.401,14.218) U6.37@-21.503,14.115 ; U6.37@-21.546,13.763 -21.546,15.508 -20.865,16.189 -20.865,18.397 v1@-20.839,18.423 ; v1@-20.967,18.294 cw(c-21.213,18.048) -20.865,18.048 ; -20.865,18.045 cw(c-20.513,18.045) v1@-20.762,18.294
  Bottom Layer w0.16: v1(-20.864,18.397) -11.014,18.397 -9.53,19.881 pad.1@-9.53,22.907 ; v1@-20.762,18.294 cw(c-20.514,18.047) -20.514,18.397 cw(c-20.514,18.747) v1@-20.762,18.499 ; pad.1@-10.181,22.257 cw(c-11.751,20.686) -9.53,20.686 cw(c-7.309,20.686) pad.1@-8.88,22.257 ; pad.1@-10.067,22.37 cw(c-11.365,21.072) -9.53,21.072 cw(c-7.695,21.072) pad.1@-8.993,22.37 ; pad.1@-9.954,22.483 cw(c-10.979,21.459) -9.53,21.459 cw(c-8.082,21.459) pad.1@-9.106,22.483 ; pad.1@-9.841,22.596 cw(c-10.592,21.845) -9.53,21.845 cw(c-8.468,21.845) pad.1@-9.219,22.596
SWDIO: pad.3 U6.34 | length 27.7
  Top Layer w0.16: U6.34@-20.847,12.064 -19.749,12.064 -19.413,12.399 -19.413,17.517 -18.452,18.478 -17.329,18.478 -17.037,18.769 -17.037,19.695 v1(-17.05,19.708) ; U6.34@-20.495,12.021 cw(c-20.392,11.919) -20.392,12.064 cw(c-20.392,12.209) U6.34@-20.495,12.106 ; v1@-17.152,19.605 cw(c-17.43,19.327) -17.037,19.327 ; -17.037,19.389 cw(c-16.73,19.389) v1@-16.947,19.605
  POWER w0.16: v1(-17.05,19.708) -17.007,19.665 -5.325,19.665 -4.529,20.461 v1(-4.529,22.907) ; v1@-16.947,19.605 cw(c-16.803,19.461) -16.803,19.665 ; v1@-16.947,19.81 ccw(c-16.597,20.161) -16.597,19.665 ; v1@-4.631,22.805 cw(c-4.879,22.557) -4.529,22.557 cw(c-4.179,22.557) v1@-4.426,22.805
VCC: C69.2 U13.9 | length 4.4
  Top Layer w0.2: C69.2@-30.822,-29.074 -30.253,-29.074 -29.779,-29.074 -29.474,-28.769 -29.474,-28.307 -28.589,-27.422 U13.9@-27.978,-27.422 ; C69.2@-30.577,-29.194 cw(c-30.287,-29.484) -30.287,-29.074 cw(c-30.287,-28.664) C69.2@-30.577,-28.954
VIN: C61.2 C78.1 F4.2 R39.2 R52.1 U9.3 U9.5 U14.3 | length 165.2
  Top Layer w0.2: C61.2@-35.496,-17.079 -34.344,-17.079 ; C61.2@-35.376,-17.199 cw(c-35.086,-17.489) -35.086,-17.079 cw(c-35.086,-16.668) C61.2@-35.376,-16.958 ; -35.082,-16.324 ccw(c-35.082,-14.944) R52.1@-33.879,-15.621 ; -35.066,-16.27 ccw(c-35.066,-14.862) R52.1@-33.867,-15.6 ; -35.029,-10.178 cw(c-35.029,-11.653) F4.2@-33.84,-10.779 ; -34.74,-16.324 ccw(c-34.74,-15.136) R52.1@-33.704,-15.719 ; -34.708,-16.27 ccw(c-34.708,-15.083) R52.1@-33.697,-15.705 ; -34.66,-10.178 ccw(c-34.66,-9.136) F4.2@-33.923,-9.873 ; -34.634,-10.178 cw(c-34.634,-11.363) F4.2@-33.679,-10.661 ; -34.448,-16.096 -35.424,-16.096 ; -34.398,-16.324 ccw(c-34.398,-15.328) R52.1@-33.53,-15.817 ; -34.398,-16.27 cw(c-34.398,-16.942) R52.1@-33.923,-16.467 ; -34.35,-16.27 ccw(c-34.35,-15.303) R52.1@-33.526,-15.81 ; -34.344,-17.079 cw(c-33.424,-17.999) R52.1@-33.388,-16.698 ; -34.268,-16.324 cw(c-34.268,-16.812) R52.1@-33.923,-16.467 ; F4.2@-34.238,-10.178 cw(c-34.238,-11.072) F4.2@-33.518,-10.542 ; R52.1@-34.154,-16.27 -35.424,-16.27 ; R52.1@-34.117,-16.148 cw(c-34.996,-16.427) -34.344,-17.079 ; -34.112,-16.846 ccw(c-34.643,-16.315) R52.1@-33.927,-16.087 ; R52.1@-34.053,-15.523 cw(c-35.424,-14.752) -35.424,-16.324 ; R52.1@-34.037,-15.496 cw(c-35.424,-14.642) -35.424,-16.27 ; R52.1@-34.016,-16.75 cw(c-33.406,-17.36) R52.1@-33.382,-16.498 ; F4.2@-34.001,-10.898 ccw(c-35.424,-11.944) -35.424,-10.178 ; R52.1@-33.923,-15.351 cw(c-35.27,-14.004) -35.27,-15.909 cw(c-35.27,-17.814) R52.1@-33.923,-16.467 ; R52.1@-33.782,-16.326 ccw(c-34.787,-17.331) -34.787,-15.909 ccw(c-34.787,-14.487) R52.1@-33.782,-15.493 ; R52.1@-33.64,-16.184 ccw(c-34.305,-16.848) -34.305,-15.909 ccw(c-34.305,-14.97) R52.1@-33.64,-15.634 ; F4.2@-33.517,-9.72 ccw(c-33.78,-9.174) -33.175,-9.174 ; R52.1@-33.498,-16.629 cw(c-33.722,-17.128) -33.175,-17.128 ; F4.2@-33.431,-9.9 ccw(c-33.627,-9.493) -33.175,-9.493 ccw(c-32.723,-9.493) F4.2@-32.919,-9.9 ; R52.1@-33.416,-16.447 cw(c-33.584,-16.819) -33.175,-16.819 cw(c-32.766,-16.819) R52.1@-32.934,-16.447 ; R52.1@-33.3,-15.909 cw(c-33.602,-15.909) -33.388,-16.123 cw(c-33.175,-16.336) R52.1@-33.175,-16.034 ; R52.1@-33.263,-15.821 cw(c-33.477,-15.607) -33.477,-15.909 cw(c-33.477,-16.211) -33.263,-15.998 cw(c-33.477,-16.211) -33.175,-16.211 cw(c-32.873,-16.211) R52.1@-33.087,-15.998 ; F4.2@-33.175,-10.43 F4.2@-33.175,-10.178 ; R52.1@-32.852,-16.629 ccw(c-32.627,-17.128) -33.175,-17.128 ; F4.2@-32.832,-9.72 cw(c-32.57,-9.174) -33.175,-9.174 ; R52.1@-32.814,-15.827 ccw(c-32.023,-15.446) -32.023,-16.324 ; R52.1@-32.709,-16.184 cw(c-32.051,-16.842) -32.051,-15.912 ; R52.1@-32.709,-15.634 ccw(c-32.039,-14.964) -32.039,-15.912 ; R52.1@-32.658,-15.698 ccw(c-31.803,-15.146) -31.803,-16.164 ; F4.2@-32.658,-10.642 cw(c-31.804,-11.195) -31.804,-10.178 ; R52.1@-32.634,-15.74 ccw(c-31.705,-15.293) -31.705,-16.324 ; R52.1@-32.568,-16.326 cw(c-31.569,-17.325) -31.569,-15.912 ; R52.1@-32.568,-15.493 ccw(c-31.556,-14.481) -31.556,-15.912 ; F4.2@-32.49,-10.751 cw(c-31.436,-11.434) -31.436,-10.178 ; R52.1@-32.49,-15.59 ccw(c-31.435,-14.909) -31.435,-16.164 ; R52.1@-32.454,-15.654 ccw(c-31.386,-15.14) -31.386,-16.324 ; R52.1@-32.426,-15.351 ccw(c-31.073,-13.998) -31.073,-15.912 ; F4.2@-32.426,-9.873 ccw(c-31.69,-9.136) -31.69,-10.178 ; F4.2@-32.322,-10.859 cw(c-31.068,-11.672) -31.068,-10.178 ; R52.1@-32.322,-15.481 ccw(c-31.068,-14.672) -31.068,-16.164 ; R52.1@-32.312,-16.321 cw(c-32.031,-16.493) -32.031,-16.164 -31.068,-16.164 ; R52.1@-32.273,-15.567 ccw(c-31.068,-14.987) -31.068,-16.324 ; R52.1@-32.146,-15.869 -32.146,-15.912 -31.068,-15.912 ; -32.082,-16.324 ccw(c-32.082,-16.812) R52.1@-32.426,-16.467 ; -31.694,-16.164 ccw(c-31.694,-17.199) R52.1@-32.426,-16.467 ; -31.659,-16.001 -31.659,-16.031 -31.068,-16.031 ; -31.086,-15.912 ccw(c-31.086,-17.808) R52.1@-32.426,-16.467 ; U14.3@-30.063,-16.572 cw(c-30.361,-16.871) -29.939,-16.871 cw(c-29.516,-16.871) U14.3@-29.815,-16.572 ; U14.3@-29.939,-16.224 -29.939,-17.14 -30.135,-17.335 -32.968,-17.335 -33.175,-17.128 ; R39.2@-26.167,-1.254 cw(c-26.457,-1.545) -26.047,-1.545 cw(c-25.637,-1.545) R39.2@-25.927,-1.254 ; R39.2@-26.047,-1.121 -26.047,-2.374 -26.524,-2.851 -29.374,-2.851 -30.047,-3.524 -30.047,-8.39 -30.62,-8.962 -32.963,-8.962 -33.175,-9.174 ; -35.424,-16.324 R52.1@-33.59,-16.324 ; -35.424,-16.324 -35.424,-16.27 ; -35.424,-16.27 -35.424,-16.096 ; -35.424,-16.096 -35.424,-15.909 ; -35.424,-15.909 -35.424,-10.178 ; -35.424,-15.909 v1(-33.175,-15.909) ; -35.424,-10.178 F4.2@-33.175,-10.178 ; -34.344,-17.079 R52.1@-33.59,-16.324 ; R52.1@-33.59,-16.324 v1(-33.175,-15.909) ; R52.1@-33.59,-16.324 R52.1@-33.175,-16.324 ; -33.175,-17.128 R52.1@-33.175,-16.324 ; R52.1@-33.175,-16.324 -31.068,-16.324 ; R52.1@-33.175,-16.324 v1(-33.175,-15.909) ; F4.2@-33.175,-10.178 -31.068,-10.178 ; F4.2@-33.175,-10.178 -33.175,-9.174 ; -31.068,-16.324 -31.068,-16.164 ; -31.068,-16.164 -31.068,-16.031 ; -31.068,-16.031 -31.068,-15.912 ; -31.068,-15.912 -31.068,-10.178
  Top Layer w0.3: U9.3@-60.591,-38.732 -59.604,-38.732 -58.654,-37.782 U9.5@-57.791,-37.782 ; U9.3@-60.278,-38.821 cw(c-60.065,-39.034) -60.065,-38.732 cw(c-60.065,-38.431) U9.3@-60.278,-38.644 ; U9.5@-58.105,-37.871 ccw(c-58.318,-38.084) -58.318,-37.782 ccw(c-58.318,-37.481) U9.5@-58.105,-37.694
  Top Layer w0.5: U9.5@-57.791,-37.782 -56.859,-37.782 -56.645,-37.997 -56.645,-39.239 -56.151,-39.733 -54.682,-39.733 -54.272,-40.143 v1(-54.272,-41.095) ; -54.554,-39.862 cw(c-55.008,-40.316) C78.1@-54.479,-40.679 ; C78.1@-54.449,-40.643 ccw(c-54.877,-40.216) -54.272,-40.216 ccw(c-53.668,-40.216) C78.1@-54.095,-40.643 ; C78.1@-54.261,-41.117 ccw(c-54.456,-40.71) -54.031,-40.861 cw(c-54.456,-40.71) C78.1@-54.261,-41.117
  Bottom Layer w0.5: v1(-54.272,-41.095) -53.853,-40.676 -53.853,-33.146 -52.807,-32.099 -40.518,-32.099 -38.771,-30.352 -38.771,-17.786 -36.893,-15.909 v1(-33.175,-15.909)
VOUT: C55.2 C62.1 C63.1 C64.1 C65.2 C66.1 C67.2 J4.A9 J4.B9 R33.2 R43.1 R49.2 R51.1 | length 144.6
  Top Layer w0.2: R33.2@-26.101,-13.559 cw(c-26.391,-13.85) -25.981,-13.85 cw(c-25.571,-13.85) R33.2@-25.861,-13.559 ; R33.2@-25.981,-13.426 -25.981,-14.857 -25.385,-15.453 -15.866,-15.453 -15.422,-15.898 -15.422,-17.907 -14.825,-18.504 -4.68,-18.504 -3.426,-19.757 -3.426,-20.234 -3.443,-20.25 -3.443,-35.231 -3.984,-35.772 -6.479,-35.772 ; -20.171,-22.72 ccw(c-19.859,-22.407) R49.2@-19.859,-22.849 ; -20.14,-22.75 cw(c-20.408,-23.019) R49.2@-20.029,-23.019 ; R49.2@-19.859,-23.032 -20.347,-22.544 -20.347,-20.968 -20.095,-20.716 ; -19.79,-20.716 ccw(c-19.79,-20.226) R51.1@-19.341,-20.422 ; -19.74,-20.716 cw(c-19.74,-21.225) R51.1@-19.305,-20.962 ; R51.1@-19.524,-20.342 cw(c-20.095,-20.094) -20.095,-20.716 ; R51.1@-19.476,-21.065 ccw(c-20.095,-21.44) -20.095,-20.716 ; R51.1@-19.311,-19.864 ccw(c-19.902,-19.168) -18.989,-19.168 ; R51.1@-19.256,-21.492 cw(c-19.62,-22.007) -18.989,-22.007 cw(c-18.601,-22.007) R51.1@-18.667,-21.625 ; R51.1@-19.164,-19.766 ccw(c-19.474,-19.168) -18.801,-19.168 ; R51.1@-19.072,-19.943 ccw(c-19.303,-19.497) -18.801,-19.497 ccw(c-18.299,-19.497) R51.1@-18.53,-19.943 ; -18.989,-21.769 cw(c-18.642,-21.769) R51.1@-18.701,-21.427 ; -18.989,-19.434 ccw(c-18.504,-19.434) R51.1@-18.638,-19.9 ; -18.741,-21.844 -18.741,-21.991 -18.989,-21.991 R51.1@-18.989,-20.716 ; R51.1@-18.583,-19.708 cw(c-18.428,-19.168) -18.989,-19.168 ; R51.1@-18.438,-19.766 cw(c-18.128,-19.168) -18.801,-19.168 ; R43.1@-17.632,-27.82 -16.981,-27.169 -15.67,-27.169 C55.2@-15.048,-27.791 -12.777,-27.791 ; R43.1@-17.619,-27.65 ccw(c-17.619,-27.27) -17.351,-27.539 ; R43.1@-17.449,-27.82 cw(c-17.007,-27.82) -17.32,-27.508 ; C55.2@-14.803,-27.912 cw(c-14.512,-28.202) -14.512,-27.791 cw(c-14.512,-27.381) C55.2@-14.803,-27.671 ; -12.479,-28.156 -12.479,-28.09 -12.586,-27.983 ; -11.919,-22.802 -12.586,-22.802 -12.586,-27.6 ; -10.615,-35.951 -10.54,-36.026 ; -10.315,-36.171 -10.395,-36.171 ; -10.282,-35.917 -12.586,-35.917 ; -10.18,-36.325 -10.241,-36.325 -10.395,-36.171 ; -9.71,-36.292 -9.661,-36.292 -9.54,-36.171 ; -9.623,-35.917 -7.254,-35.917 ; -9.409,-27.584 -9.616,-27.791 -12.586,-27.791 ; -9.335,-35.965 -9.395,-36.026 ; -8.86,-35.005 -8.86,-35.063 -8.733,-35.19 ; -8.754,-35.556 -8.733,-35.556 -8.733,-35.19 ; -8.415,-35.508 -8.733,-35.19 ; -7.596,-35.979 -7.471,-35.979 -7.424,-36.026 ; -7.254,-35.679 -7.254,-35.917 ; -7.101,-36.35 -7.285,-36.166 ; -7.017,-36.511 -7.362,-36.166 ; -6.993,-35.757 -6.977,-35.772 -6.496,-35.772 ; -6.888,-36.131 -6.888,-36.166 -7.285,-36.166 ; -6.665,-35.603 -6.496,-35.772 ; -6.656,-35.949 -6.479,-35.772 ; -20.095,-20.716 R51.1@-18.989,-20.716 ; R51.1@-18.989,-20.716 -18.989,-19.168 ; R51.1@-18.989,-20.716 -18.861,-20.716 R51.1@-18.801,-20.656 -18.801,-19.168 ; -18.989,-19.168 -18.801,-19.168 ; -18.801,-19.168 -8.733,-19.168 -8.733,-35.19 ; -12.777,-27.791 -12.586,-27.983 ; -12.777,-27.791 -12.586,-27.791 ; -12.777,-27.791 -12.586,-27.6 ; -12.586,-36.026 -12.586,-36.171 -10.395,-36.171 ; -12.586,-36.026 -12.586,-35.917 ; -12.586,-36.026 -10.54,-36.026 ; -12.586,-35.917 -12.586,-27.983 ; -12.586,-27.983 -12.586,-27.791 ; -12.586,-27.791 -12.586,-27.6 ; -10.54,-36.026 -10.395,-36.171 ; -10.54,-36.026 -9.395,-36.026 ; -10.395,-36.171 -9.54,-36.171 ; -9.54,-36.171 -9.395,-36.026 ; -9.54,-36.171 -8.763,-36.171 -8.763,-36.166 -7.362,-36.166 ; -9.395,-36.026 -7.424,-36.026 ; -7.424,-36.026 -7.285,-36.166 ; -7.424,-36.026 -7.254,-36.026 -7.254,-35.917 ; -7.362,-36.166 -7.285,-36.166 ; -6.496,-35.772 -6.479,-35.772
  Top Layer w0.5: R51.1@-19.041,-19.874 ccw(c-19.22,-19.43) -18.741,-19.43 ; R51.1@-19.02,-21.447 cw(c-19.166,-21.846) -18.741,-21.846 cw(c-18.23,-21.846) R51.1@-18.484,-21.402 ; -18.543,-19.43 -18.741,-19.43 ; R51.1@-18.466,-19.922 cw(c-18.164,-19.43) -18.741,-19.43 ; -17.673,-21.844 -18.741,-21.844 -18.741,-19.43
  Top Layer w1: -13.552,-21.321 -13.4,-21.321 -11.919,-22.802
  other v1: -10.022,-34.261 -9.23,-29.204 -10.022,-25.609 -9.33,-20.667
VREF: C17.2 Q3.3 R13.2 R18.2 U3.8 | length 45
  Top Layer w0.3: R18.2@-72.618,-24.771 ccw(c-73.149,-25.252) -73.149,-24.536 ; R18.2@-72.618,-24.301 cw(c-73.149,-23.82) -73.149,-24.536 ; R18.2@-72.358,-24.536 -73.149,-24.536 ; Q3.3@-70.371,-15.257 ccw(c-70.627,-15.513) -70.627,-15.151 ccw(c-70.627,-14.789) Q3.3@-70.371,-15.045 ; Q3.3@-69.458,-15.257 cw(c-69.202,-15.513) -69.202,-15.151 cw(c-69.202,-14.789) Q3.3@-69.458,-15.045 ; U3.8@-61.952,-22.92 -58.865,-22.92 C17.2@-58.461,-22.515 -58.461,-20.56 R13.2@-58.359,-20.458 -58.359,-18.971 -59.187,-18.143 -67.561,-18.143 -68.271,-17.433 -68.271,-15.383 -68.504,-15.151 Q3.3@-69.915,-15.151 -73.019,-15.151 -73.737,-15.87 -73.737,-23.947 -73.149,-24.536 ; U3.8@-61.217,-23.036 cw(c-60.936,-23.318) -60.936,-22.92 cw(c-60.936,-22.521) U3.8@-61.217,-22.803 ; -60.161,-22.92 ccw(c-60.161,-20.865) C17.2@-58.708,-22.318 ; -59.437,-22.92 ccw(c-59.437,-21.59) C17.2@-58.496,-22.53 ; C17.2@-58.708,-22.216 ccw(c-59.307,-21.618) -58.461,-21.618 ccw(c-57.615,-21.618) C17.2@-58.213,-22.216 ; R13.2@-58.607,-20.757 cw(c-58.96,-21.11) -58.461,-21.11 ; R13.2@-58.607,-20.16 ccw(c-59.205,-19.562) -58.359,-19.562 ccw(c-57.513,-19.562) R13.2@-58.111,-20.16 ; -58.461,-21.6 cw(c-57.268,-21.6) R13.2@-58.111,-20.757
VSET: C73.1 R55.2 R56.1 U13.8 | length 9.4
  Top Layer w0.16: C73.1@-31.082,-25.53 cw(c-31.437,-25.886) -30.935,-25.886 ; R56.1@-31.069,-27.714 ccw(c-31.393,-27.389) -30.935,-27.389 ccw(c-30.476,-27.389) R56.1@-30.8,-27.714 ; R55.2@-31.069,-26.756 cw(c-31.393,-27.081) -30.935,-27.081 cw(c-30.476,-27.081) R55.2@-30.8,-26.756 ; R55.2@-31.069,-26.488 ccw(c-31.393,-26.163) -30.935,-26.163 ccw(c-30.476,-26.163) R55.2@-30.8,-26.488 ; -30.935,-25.824 cw(c-30.52,-25.824) C73.1@-30.813,-25.53 ; C73.1@-30.822,-25.396 -30.935,-25.508 R55.2@-30.935,-26.622 R56.1@-30.935,-27.848 -29.576,-27.848 -28.75,-27.022 U13.8@-27.978,-27.022 ; R56.1@-30.788,-27.982 cw(c-30.463,-28.307) -30.463,-27.848 cw(c-30.463,-27.389) R56.1@-30.788,-27.714
pads on no net: F2.3 F3.2 J1. J4.A5 J4.B5 T1.2 T1.10 U1.4 U1.6 U6.2 U6.3 U6.4 U6.16 U6.18 U6.19 U6.21 U6.26 U6.27 U6.28 U6.29 U6.46 U8.4 U10.4 U12.2 U13.7 U13.10 U13.15

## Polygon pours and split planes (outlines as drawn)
GND on Top Layer "Top Layer-No Net" (solid, remove dead copper, pour order 60): -8.288,-19.172 -8.288,-19.181 -6.504,-19.181 -5.23,-19.181 -5.23,-20.669 -5.23,-35.135 -6.759,-35.135 -7.691,-35.135 -7.691,-34.799 -7.691,-35.118 -8.071,-35.118 -8.277,-35.118 -8.277,-19.177
NetR50_2 on Top Layer "Top Layer-No Net" (solid, remove dead copper, pour order 55): -25.606,-26.592 -25.075,-26.592 -24.681,-26.592 -24.681,-26.106 -24.681,-22.193 -22.072,-22.193 -22.031,-22.193 -22.031,-19.201 -22.031,-19.192 -24.16,-19.192 -25.607,-19.192 -25.607,-26.591
NetC61_1 on Top Layer "Top Layer-No Net" (solid, remove dead copper, pour order 54): -34.642,-19.305 -34.642,-19.313 -31.746,-19.313 -31.511,-19.313 -31.511,-19.666 -31.511,-22.977 -31.178,-22.977 -26.821,-22.977 -26.821,-24.597 -26.821,-26.598 -27.353,-26.598 -27.445,-26.598 -27.445,-26.077 -27.445,-24.652 -28.2,-24.652 -34.637,-24.652 -34.637,-19.309
GND on Top Layer "Top Layer-No Net" (solid, remove dead copper, pour order 53): -26.784,-26.599 -26.784,-26.604 -25.952,-26.604 -25.735,-26.604 -25.735,-26.366 -25.735,-22.041 -26.241,-22.041 -26.783,-22.041 -26.783,-26.606
VOUT on Top Layer "Top Layer-No Net" (solid, remove dead copper, pour order 52): -12.587,-32.942 -12.586,-32.942 -12.586,-35.485 -12.586,-35.913 -10.546,-35.913 -10.35,-35.913 -10.35,-36.687 -10.35,-37.787 -9.55,-37.787 -9.55,-36.687 -9.548,-36.687 -9.548,-35.965 -9.548,-35.923 -9.458,-35.923 -7.309,-35.923 -7.309,-36.687 -7.309,-37.787 -6.509,-37.787 -6.509,-36.687 -6.51,-36.687 -6.51,-35.347 -6.51,-35.391 -8.636,-35.391 -8.688,-35.391 -8.688,-32.942
VOUT on Top Layer "Top Layer-No Net" (solid, remove dead copper, pour order 50): -18.559,-18.819 -18.559,-21.81 -18.064,-21.81 -12.587,-21.81 -12.587,-23.399 -12.587,-32.942 -9.262,-32.942 -8.688,-32.942 -8.688,-30.489 -8.688,-18.824 -18.559,-18.824
NetQ2_3 on Top Layer "Top Layer-No Net" (solid, remove dead copper, pour order 32): -73.412,-7.889 -71.669,-7.889 -71.669,-9.111 -71.669,-9.12 -67.211,-9.12 -67.211,-11.012 -71.669,-11.012 -73.41,-11.012 -73.41,-7.89
PGND on Top Layer "Top Layer-No Net" (solid, remove dead copper, pour order 51): -83.88,16.649 -83.87,16.638 -83.87,15.066 -83.87,14.683 -83.557,14.37 -83.547,14.36 -82.246,14.36 -81.087,14.36 -80.462,14.985 -80.109,15.338 -79.061,15.338 -72.306,15.338 -71.904,15.74 -71.703,15.941 -71.703,17.041 -71.703,17.324 -72.075,17.696 -72.166,17.788 -73.285,17.788 -82.979,17.788 -83.711,17.056 -83.867,16.9 -83.867,16.603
